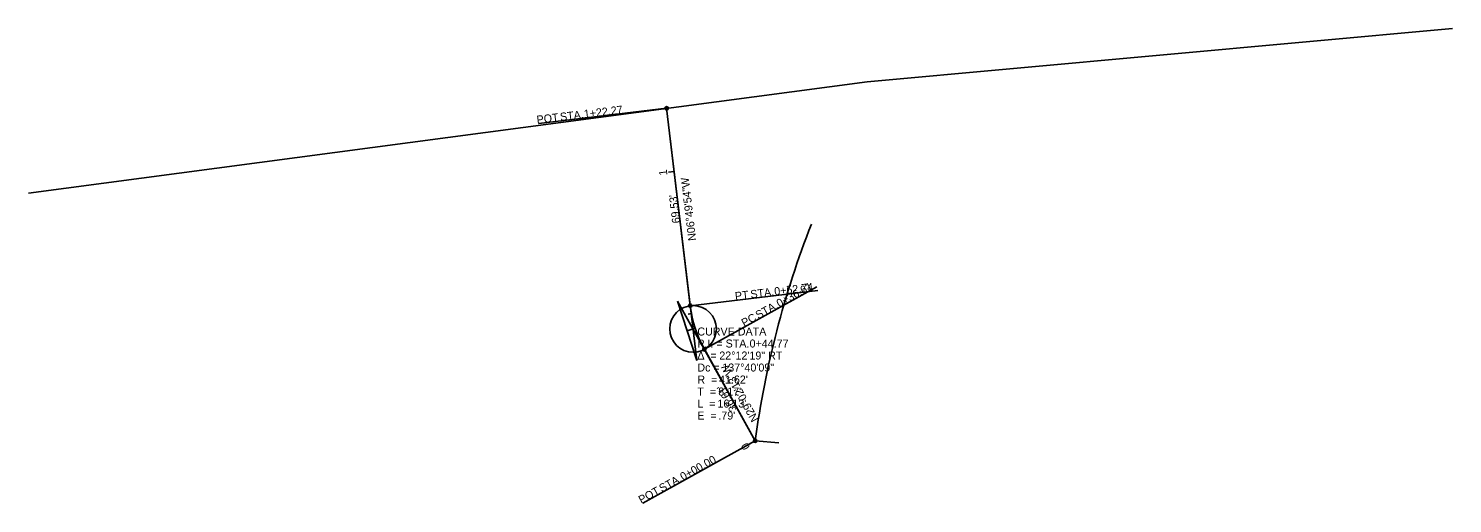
# Model space of a CAD drawing. Extents: x 226970 to 227468, y 294183 to 294349.
import ezdxf

# ---------------------------------------------------------------- set-up
doc = ezdxf.new("R2010")
doc.units = 0
for name, color, linetype in [('GE_P_Alignment', 7, 'Continuous'), ('GE_P_Alignment_100_Bearings', 7, 'Continuous'), ('GE_P_Alignment_100_Cardinal_Points', 7, 'Continuous'), ('GE_P_Alignment_100_Curve_Data', 7, 'Continuous'), ('GE_P_Alignment_100_Distances', 7, 'Continuous'), ('SC_Scratch1', 7, 'Continuous'), ('SC_Scratch2', 7, 'Continuous')]:
    doc.layers.add(name, color=color, linetype=linetype)

msp = doc.modelspace()

# ---------------------------------------------------------------- linework, layer by layer
at = {"layer": 'GE_P_Alignment'}
for p, q in [((227201.14, 294252.37), (227192.87, 294321.41)), ((227223.84, 294205.12), (227206.08, 294237.12))]:
    msp.add_line(p, q, dxfattribs=at)
msp.add_arc((227242.46, 294257.32), 41.62, 186.8316, 209.0369, dxfattribs=at)
msp.add_arc((227242.46, 294257.32), 41.62, 186.8316, 209.0369, dxfattribs=at)
at = {"layer": 'GE_P_Alignment_100_Bearings'}
for p, q in [((227192.87, 294321.41), (227148.19, 294316.05)), ((227201.14, 294252.37), (227245.82, 294257.73)), ((227206.08, 294237.12), (227245.42, 294258.96)), ((227223.84, 294205.12), (227184.5, 294183.28))]:
    msp.add_line(p, q, dxfattribs=at)
for centre in [(227192.87, 294321.41), (227201.14, 294252.37), (227206.08, 294237.12), (227223.84, 294205.12)]:
    msp.add_circle(centre, 0.6, dxfattribs=at)
at = {"layer": 'GE_P_Alignment_100_Distances'}
for p, q in [((227195.52, 294299.3), (227193.53, 294299.06)), ((227201.56, 294249.67), (227200.38, 294249.45)), ((227223.84, 294205.12), (227222.1, 294204.15))]:
    msp.add_line(p, q, dxfattribs=at)
at = {"layer": 'SC_Scratch1'}
for p, q in [((227263.03, 294330.73), (227467.8, 294349.33)), ((226969.62, 294291.73), (227263.03, 294330.73)), ((227192.87, 294321.41), (227203.44, 294233.22)), ((227223.84, 294205.12), (227196.72, 294253.98)), ((227196.72, 294253.98), (227203.44, 294233.22)), ((227200.08, 294243.6), (227202.87, 294244.51)), ((227223.84, 294205.12), (227232.12, 294204.46))]:
    msp.add_line(p, q, dxfattribs=at)
msp.add_circle((227202.11, 294244.26), 8.17, dxfattribs=at)
msp.add_arc((227548.9, 294161.26), 328, 158.6027, 172.3155, dxfattribs=at)

# ---------------------------------------------------------------- texts
at = {"layer": 'GE_P_Alignment_100_Bearings'}
for s, rotation, p in [(' STA. ', 6.8316, (227154.71, 294316.88)), ('1+22.27', 6.8316, (227164.09, 294318)), ('POT', 6.8316, (227147.56, 294316.02)), ('PT', 6.8316, (227216.93, 294254.31)), (' STA. ', 6.8316, (227221.31, 294254.83)), ('0+52.74', 6.8316, (227230.69, 294255.96)), ('0+36.61', 29.0369, (227232.26, 294251.71)), (' STA. ', 29.0369, (227224, 294247.12)), ('PC', 29.0369, (227219.99, 294244.9)), ('0+00.00', 29.0369, (227198.55, 294191.12)), (' STA. ', 29.0369, (227190.28, 294186.53)), ('POT', 29.0369, (227183.99, 294183.04))]:
    msp.add_text(s, height=2.8, rotation=rotation, dxfattribs=at).set_placement(p)
at = {"layer": 'GE_P_Alignment_100_Cardinal_Points'}
for s, p in [('CURVE DATA', (227203.61, 294241.95)), ('P.I. = STA. ', (227203.61, 294237.75)), ('0+44.77', (227221.88, 294237.75)), ('Δ  = ', (227203.61, 294233.55)), ('22°12\'19" RT', (227211.29, 294233.55)), ('Dc = ', (227203.61, 294229.35)), ('137°40\'09"', (227212.35, 294229.35)), ('R  = ', (227203.61, 294225.15)), ("41.62'", (227211.19, 294225.15)), ('T  = ', (227203.61, 294220.95)), ("8.17'", (227210.95, 294220.95)), ('L  = ', (227203.61, 294216.75)), ("16.13'", (227210.65, 294216.75)), ('E  = ', (227203.61, 294212.55)), (".79'", (227210.95, 294212.55))]:
    msp.add_text(s, height=2.8, dxfattribs=at).set_placement(p)
at = {"layer": 'GE_P_Alignment_100_Curve_Data'}
for s, rotation, p in [("69.53'", 96.8316, (227197.63, 294281.36)), ("36.61'", 119.0369, (227217.62, 294216.24))]:
    msp.add_text(s, height=2.8, rotation=rotation, dxfattribs=at).set_placement(p)
at = {"layer": 'GE_P_Alignment_100_Distances'}
for s, rotation, p in [('1', 96.8316, (227193.15, 294298.09)), ('0', 119.0369, (227222.2, 294202.93))]:
    msp.add_text(s, height=2.8, rotation=rotation, dxfattribs=at).set_placement(p)
at = {"layer": 'SC_Scratch2'}
for s, rotation, p in [('N06°49\'54"W', 96.8316, (227203.24, 294275.23)), ('N29°02\'13"W', 119.0369, (227225.13, 294212.68))]:
    msp.add_text(s, height=2.8, rotation=rotation, dxfattribs=at).set_placement(p)

doc.saveas('drawing.dxf')
